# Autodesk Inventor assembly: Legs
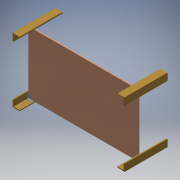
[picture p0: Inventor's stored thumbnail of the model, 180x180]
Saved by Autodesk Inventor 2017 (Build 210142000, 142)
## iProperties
Created: 2017-05
Part Number: Legs
Document SubType Name: Assembly
Designer: Savy
Author: Savy
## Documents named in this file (3)
- D:\Users\Savy\Documents\Infinity Table\Legs.iam
- D:\Users\Savy\Documents\Infinity Table\Shelf.ipt
- D:\Users\Savy\Documents\Infinity Table\LegAssm1.iam
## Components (5 placed, 5 different names)
1. Shelf_1017
2. LegAssm1_1018 [sub-assembly]
3. LegAssm1_1019 [sub-assembly]
4. LegAssm1_1020 [sub-assembly]
5. LegAssm1_1021 [sub-assembly]
